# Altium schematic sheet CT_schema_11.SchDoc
size 389 x 278 mm
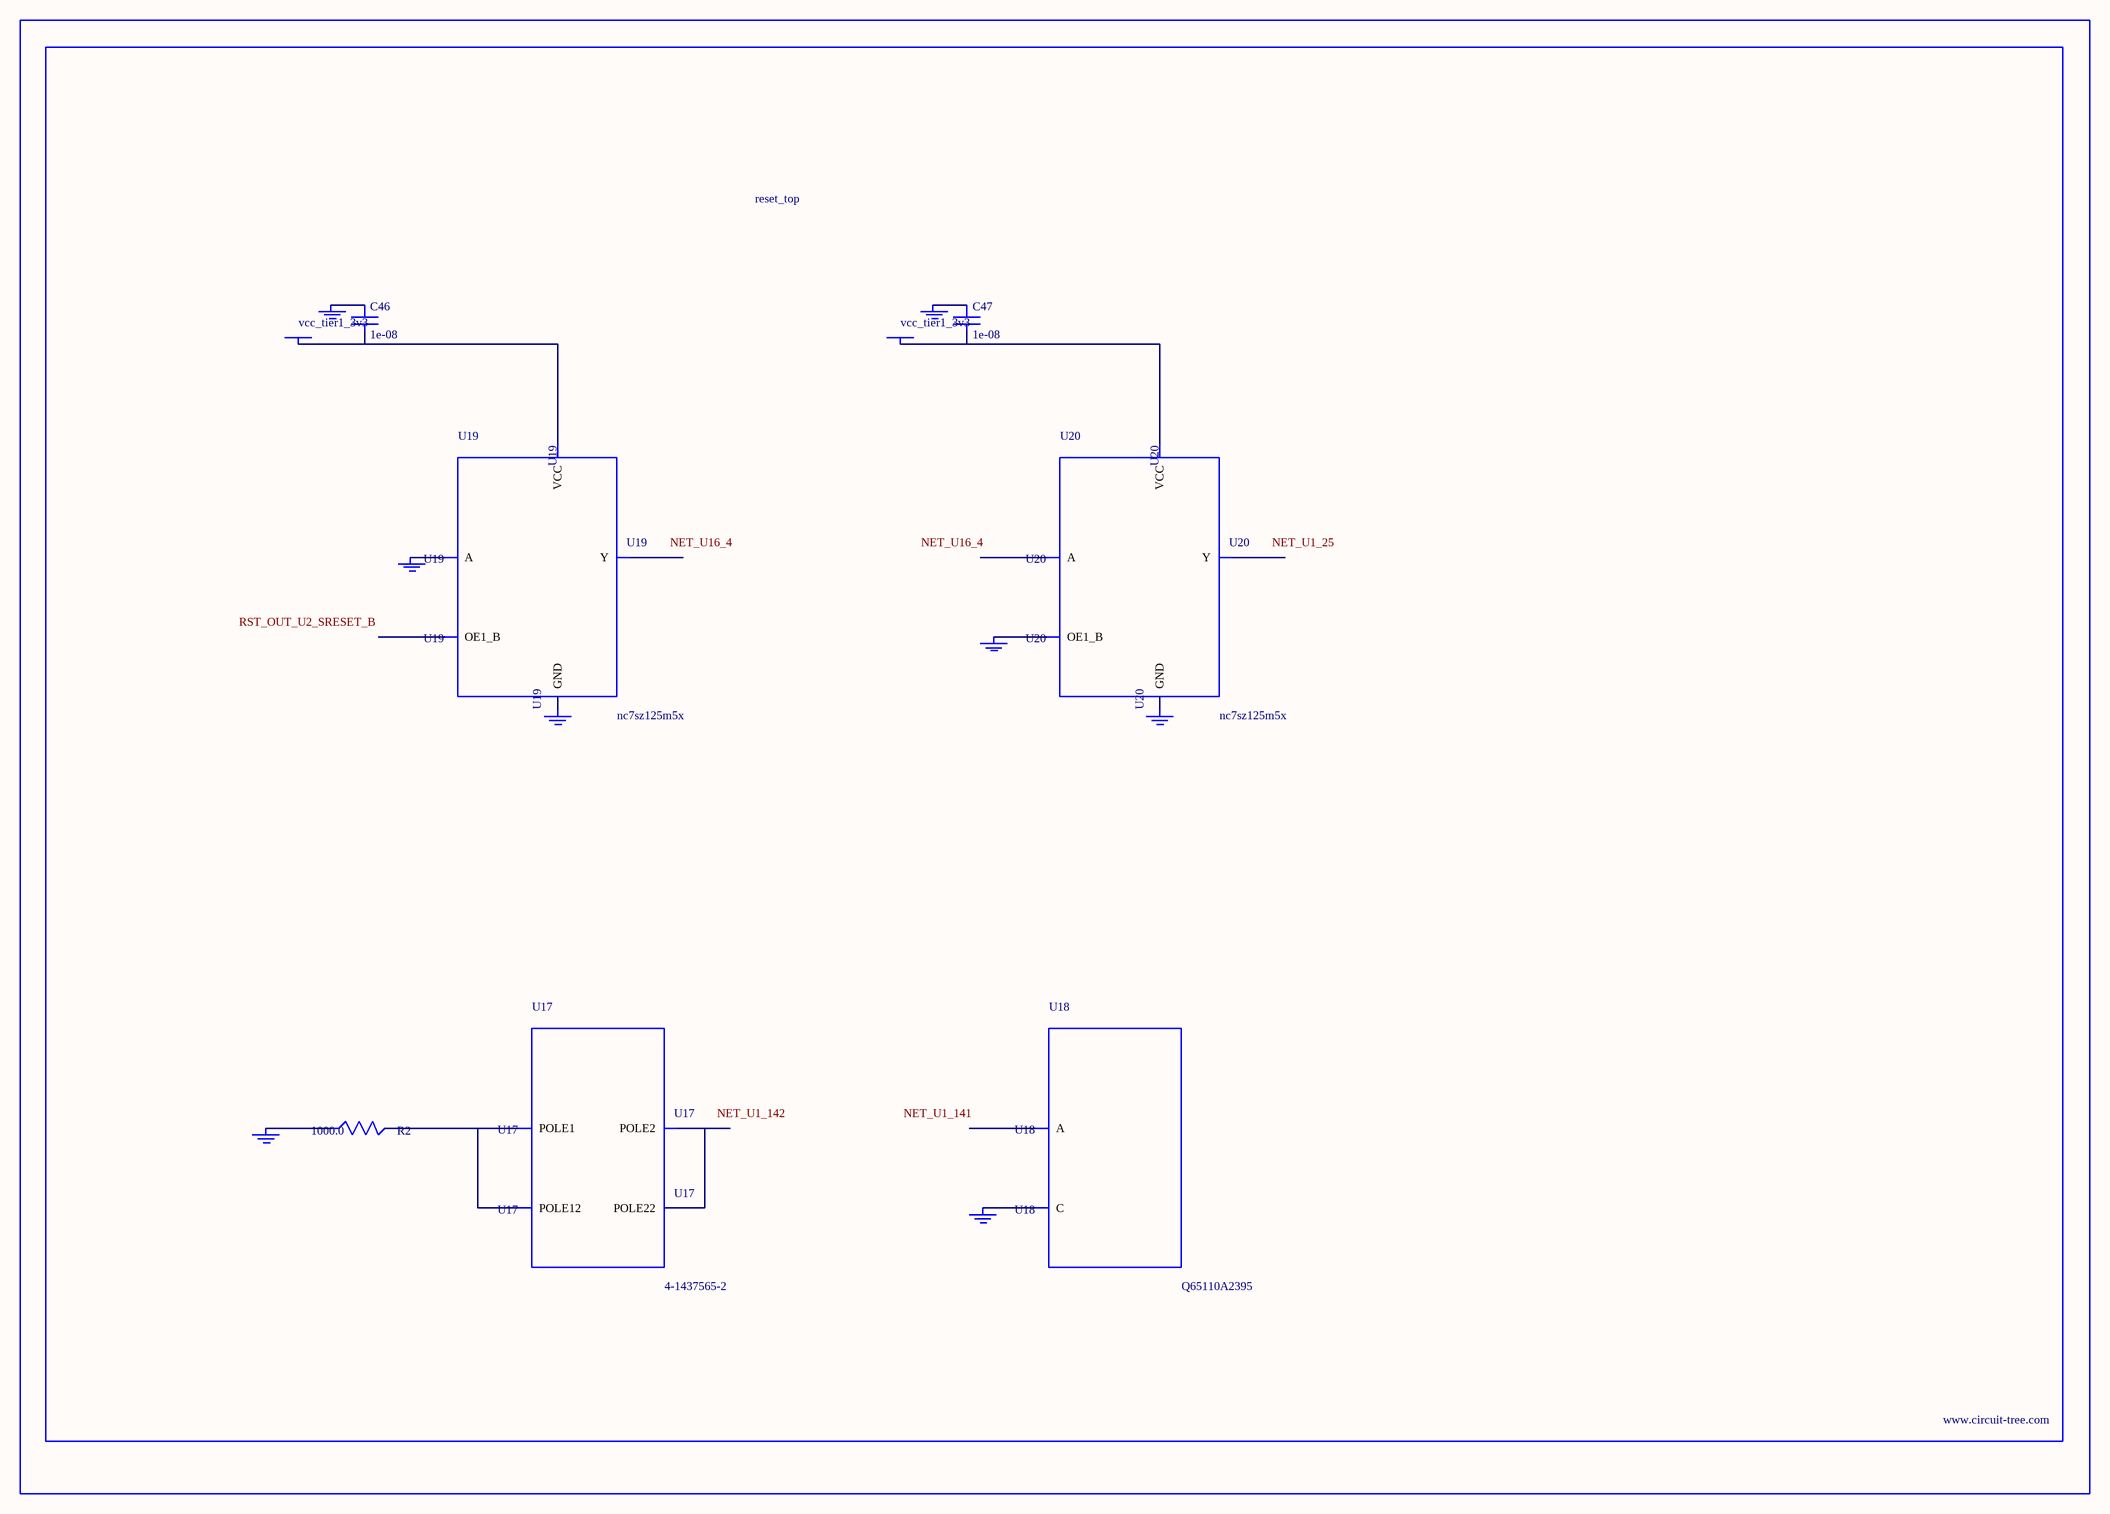
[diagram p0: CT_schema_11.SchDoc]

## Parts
BORDER10  (no value)
C46  1e-08  [C0402]
C47  1e-08  [C0402]
GND_INSTANCE_10_0  (no value)
GND_INSTANCE_10_1  (no value)
GND_INSTANCE_10_2  (no value)
GND_INSTANCE_10_3  (no value)
GND_INSTANCE_10_4  (no value)
GND_INSTANCE_10_5  (no value)
GND_INSTANCE_10_6  (no value)
GND_INSTANCE_10_7  (no value)
POWER_INSTANCE_10_0  vcc_tier1_3v3
POWER_INSTANCE_10_1  vcc_tier1_3v3
R2  1000.0  [R0603]
U17  4-1437565-2  [SW_4-1437565-2]
U18  Q65110A2395  [LGM67K-G1J2-24-Z]
U19  nc7sz125m5x  [NC7SZ125M5X]
U20  nc7sz125m5x  [NC7SZ125M5X]

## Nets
NetC46_1: C46.1 GND_INSTANCE_10_2.0(GND)
NetC46_2: C46.2 POWER_INSTANCE_10_0.0(PWR) U19.5(VCC)
NetC47_1: C47.1 GND_INSTANCE_10_5.0(GND)
NetC47_2: C47.2 POWER_INSTANCE_10_1.0(PWR) U20.5(VCC)
NetGND_INSTANCE_10_0_0: GND_INSTANCE_10_0.0(GND) R2.1
NetGND_INSTANCE_10_1_0: GND_INSTANCE_10_1.0(GND) U18.C
NetGND_INSTANCE_10_3_0: GND_INSTANCE_10_3.0(GND) U19.2(A)
NetGND_INSTANCE_10_4_0: GND_INSTANCE_10_4.0(GND) U19.3(GND)
NetGND_INSTANCE_10_6_0: GND_INSTANCE_10_6.0(GND) U20.1(OE1_B)
NetGND_INSTANCE_10_7_0: GND_INSTANCE_10_7.0(GND) U20.3(GND)
NetR2_2: R2.2 U17.1(POLE1) U17.2(POLE12)
NetU17_3: U17.3(POLE2) U17.4(POLE22)

Not connected (* = marked no-connect by the designer): U18 A; U19 1(OE1_B) 4(Y); U20 2(A) 4(Y)

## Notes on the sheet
- Labels drawn without touching a wire or pin: NET_U1_25, NET_U1_141, NET_U1_142, NET_U16_4, RST_OUT_U2_SRESET_B

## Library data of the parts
BORDER10 = BORDER_PAGE10
C46 C47 = C0402C103K3RAC
GND_INSTANCE_10_0-GND_INSTANCE_10_7 = GND
POWER_INSTANCE_10_0 POWER_INSTANCE_10_1 = PWR
R2 = RC0603JR-071KL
